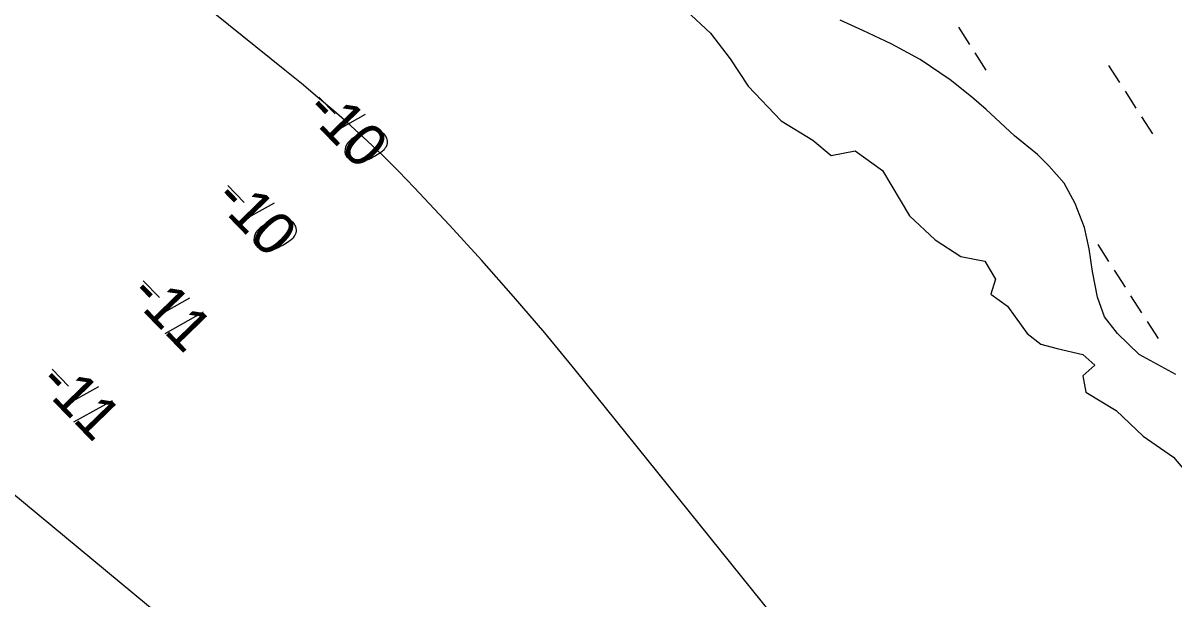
# Model space of a CAD drawing. Extents: x 3962991 to 3983549, y 181631 to 204078.
# Drawn here: x 3974291 to 3975197, y 193277 to 193730 of the extents above; entities that cross this region are included whole.
import ezdxf

# ---------------------------------------------------------------- set-up
doc = ezdxf.new("R2010")
doc.units = 0
for name, color, linetype in [('V-ANNO-MASK', 7, 'Continuous'), ('V-ANNO-MASK2', 7, 'Continuous'), ('V-RIVR-EDGE', 7, 'Continuous'), ('V-RIVR-RANG', 7, 'Continuous'), ('V-TOPO-DPTH', 7, 'Continuous'), ('V-TOPO-MINR', 7, 'Continuous'), ('V-WETL-SWMP', 7, 'Continuous')]:
    doc.layers.add(name, color=color, linetype=linetype)

msp = doc.modelspace()

# ---------------------------------------------------------------- linework, layer by layer
at = {"layer": 'V-ANNO-MASK2'}
for p, q in [((3974524.19, 193672.13), (3974537.05, 193658.88)), ((3974560.73, 193658.34), (3974530.45, 193641.44)), ((3974452.5, 193602.54), (3974465.36, 193589.3)), ((3974489.05, 193588.76), (3974458.76, 193571.86)), ((3974385.89, 193527.59), (3974398.75, 193514.34)), ((3974422.44, 193513.81), (3974392.15, 193496.91)), ((3974433.09, 193502.83), (3974402.81, 193485.93)), ((3974314.14, 193457.94), (3974327, 193444.69)), ((3974350.68, 193444.15), (3974320.4, 193427.26)), ((3974361.34, 193433.18), (3974331.05, 193416.28))]:
    msp.add_line(p, q, dxfattribs=at)
for points in [[(3974576.16, 193642.44), (3974575.8, 193642.82), (3974574.5, 193643.77), (3974573.58, 193644.34), (3974572.84, 193644.73), (3974571.54, 193645.31), (3974569.87, 193645.89), (3974568.39, 193646.29), (3974566.71, 193646.5), (3974565.4, 193646.33), (3974563.9, 193645.98), (3974562.41, 193645.63), (3974560.72, 193645.09), (3974559.59, 193644.74), (3974558.09, 193644.01), (3974555.65, 193642.74), (3974552.26, 193640.56), (3974549.62, 193638.73), (3974547.54, 193636.71), (3974546.21, 193635.05), (3974545.24, 193632.64), (3974544.84, 193631.15), (3974544.63, 193629.1), (3974544.97, 193627.23), (3974545.33, 193626.48), (3974546.25, 193625.16), (3974547.16, 193624.22), (3974548.82, 193622.89), (3974550.49, 193621.93), (3974551.97, 193621.53), (3974554.21, 193621.13), (3974555.33, 193621.11), (3974556.82, 193621.09), (3974558.13, 193621.26), (3974559.06, 193621.43), (3974560.38, 193621.97), (3974560.94, 193622.15), (3974562.25, 193622.69), (3974563.75, 193623.41), (3974565.26, 193624.13), (3974566.2, 193624.68), (3974566.95, 193625.04), (3974567.89, 193625.59), (3974569.96, 193626.86), (3974571.09, 193627.59), (3974572.22, 193628.32), (3974573.73, 193629.42), (3974575.62, 193630.88), (3974576.19, 193631.43), (3974576.76, 193632.36), (3974577.33, 193633.28), (3974577.92, 193634.95), (3974578.12, 193636.25), (3974578.14, 193637.37), (3974577.97, 193638.68), (3974577.62, 193639.81), (3974577.25, 193640.56), (3974576.89, 193641.31), (3974576.16, 193642.44)], [(3974504.48, 193572.86), (3974504.11, 193573.24), (3974502.82, 193574.19), (3974501.9, 193574.76), (3974501.16, 193575.15), (3974499.86, 193575.72), (3974498.19, 193576.31), (3974496.7, 193576.7), (3974495.03, 193576.92), (3974493.72, 193576.75), (3974492.22, 193576.4), (3974490.72, 193576.05), (3974489.04, 193575.51), (3974487.91, 193575.16), (3974486.41, 193574.43), (3974483.97, 193573.16), (3974480.57, 193570.97), (3974477.94, 193569.15), (3974475.85, 193567.13), (3974474.52, 193565.47), (3974473.56, 193563.06), (3974473.16, 193561.57), (3974472.94, 193559.52), (3974473.29, 193557.65), (3974473.65, 193556.9), (3974474.56, 193555.58), (3974475.48, 193554.63), (3974477.14, 193553.3), (3974478.81, 193552.35), (3974480.29, 193551.95), (3974482.52, 193551.55), (3974483.64, 193551.53), (3974485.14, 193551.51), (3974486.44, 193551.67), (3974487.38, 193551.85), (3974488.69, 193552.39), (3974489.25, 193552.56), (3974490.57, 193553.1), (3974492.07, 193553.83), (3974493.57, 193554.55), (3974494.52, 193555.1), (3974495.27, 193555.46), (3974496.21, 193556.01), (3974498.28, 193557.28), (3974499.41, 193558.01), (3974500.54, 193558.74), (3974502.05, 193559.84), (3974503.94, 193561.3), (3974504.5, 193561.85), (3974505.08, 193562.78), (3974505.65, 193563.7), (3974506.23, 193565.37), (3974506.44, 193566.67), (3974506.46, 193567.79), (3974506.29, 193569.1), (3974505.93, 193570.22), (3974505.57, 193570.98), (3974505.21, 193571.73), (3974504.48, 193572.86)]]:
    msp.add_lwpolyline(points, dxfattribs=at)
at = {"layer": 'V-RIVR-EDGE'}
msp.add_lwpolyline([(3974813.41, 193740.22), (3974832.41, 193722.41), (3974847.84, 193702.23), (3974862.09, 193680.86), (3974888.2, 193653.55), (3974913.14, 193638.12), (3974927.38, 193626.24), (3974946.38, 193629.81), (3974967.75, 193614.37), (3974989.12, 193578.76), (3975009.3, 193559.76), (3975029.48, 193546.7), (3975048.48, 193543.14), (3975056.79, 193528.89), (3975053.23, 193517.02), (3975066.29, 193507.52), (3975072.22, 193499.21), (3975081.72, 193486.15), (3975092.4, 193477.84), (3975105.46, 193474.28), (3975125.65, 193469.53), (3975135.14, 193461.22), (3975125.65, 193452.91), (3975128.02, 193439.85), (3975151.77, 193425.61), (3975173.14, 193405.42), (3975196.88, 193388.8), (3975217.06, 193365.06)], dxfattribs=at)
at = {"layer": 'V-TOPO-DPTH'}
for points in [[(3975036.15, 193072.49), (3974725.93, 193457.49), (3974701.94, 193486.6), (3974677.52, 193515.33), (3974652.46, 193543.51), (3974626.98, 193571.31), (3974599.11, 193601.06), (3974587.08, 193613.54), (3974574.83, 193625.8), (3974562.24, 193637.72), (3974549.43, 193649.4), (3974548.48, 193650.25), (3974535.9, 193661.25), (3974523.22, 193672.12), (3974510.38, 193682.81), (3974497.44, 193693.37), (3973960.92, 194124.77)], [(3974271.51, 193369.82), (3974442.17, 193228.56)]]:
    msp.add_lwpolyline(points, dxfattribs=at)
at = {"layer": 'V-TOPO-MINR'}
for points in [[(3975036.15, 193072.49), (3974725.93, 193457.49), (3974701.94, 193486.6), (3974677.52, 193515.33), (3974652.46, 193543.51), (3974626.98, 193571.31), (3974599.11, 193601.06), (3974587.08, 193613.54), (3974574.83, 193625.8), (3974562.24, 193637.72), (3974549.43, 193649.4), (3974548.48, 193650.25), (3974535.9, 193661.25), (3974523.22, 193672.12), (3974510.38, 193682.81), (3974497.44, 193693.37), (3973960.92, 194124.77)], [(3974271.51, 193369.82), (3974442.17, 193228.56)]]:
    msp.add_lwpolyline(points, dxfattribs=at)
at = {"layer": 'V-WETL-SWMP'}
for p, q in [((3975027.72, 193727.05), (3975036.35, 193713.59)), ((3975040.67, 193706.85), (3975049.31, 193693.38)), ((3975145.81, 193697.1), (3975154.45, 193683.63)), ((3975158.77, 193676.89), (3975167.4, 193663.43)), ((3975171.72, 193656.69), (3975180.35, 193643.22)), ((3975137.25, 193556.2), (3975145.89, 193542.73)), ((3975150.21, 193535.99), (3975158.84, 193522.52)), ((3975163.16, 193515.79), (3975171.8, 193502.32)), ((3975176.11, 193495.58), (3975184.75, 193482.11))]:
    msp.add_line(p, q, dxfattribs=at)
msp.add_lwpolyline([(3975198.71, 193453.79), (3975169.86, 193469.57), (3975152.95, 193486.1), (3975142.64, 193499.12), (3975137.09, 193514.58), (3975133.27, 193534.84), (3975130.67, 193552.72), (3975126.9, 193569.4), (3975119.51, 193588.42), (3975110.96, 193604.45), (3975098.86, 193618.04), (3975089.8, 193626.89), (3975071.71, 193641.61), (3975049.37, 193662.25), (3975037.91, 193672.27), (3975021.03, 193685.81), (3974997.56, 193701.66), (3974974.72, 193713.94), (3974952.5, 193724.43), (3974934.49, 193732.58)], dxfattribs=at)

# ---------------------------------------------------------------- texts
at = {"layer": 'V-ANNO-MASK'}
for s, p in [('-10', (3974512.07, 193660.37)), ('-10', (3974440.39, 193590.79)), ('-11', (3974373.78, 193515.83)), ('-11', (3974302.03, 193446.18))]:
    msp.add_text(s, height=33.5, rotation=314.14786, dxfattribs=at).set_placement(p)
at = {"layer": 'V-RIVR-RANG'}
for s, p in [('-10', (3974512.07, 193660.37)), ('-10', (3974440.39, 193590.79)), ('-11', (3974373.78, 193515.83)), ('-11', (3974302.03, 193446.18))]:
    msp.add_text(s, height=33.5, rotation=314.14786, dxfattribs=at).set_placement(p)

doc.saveas('drawing.dxf')
